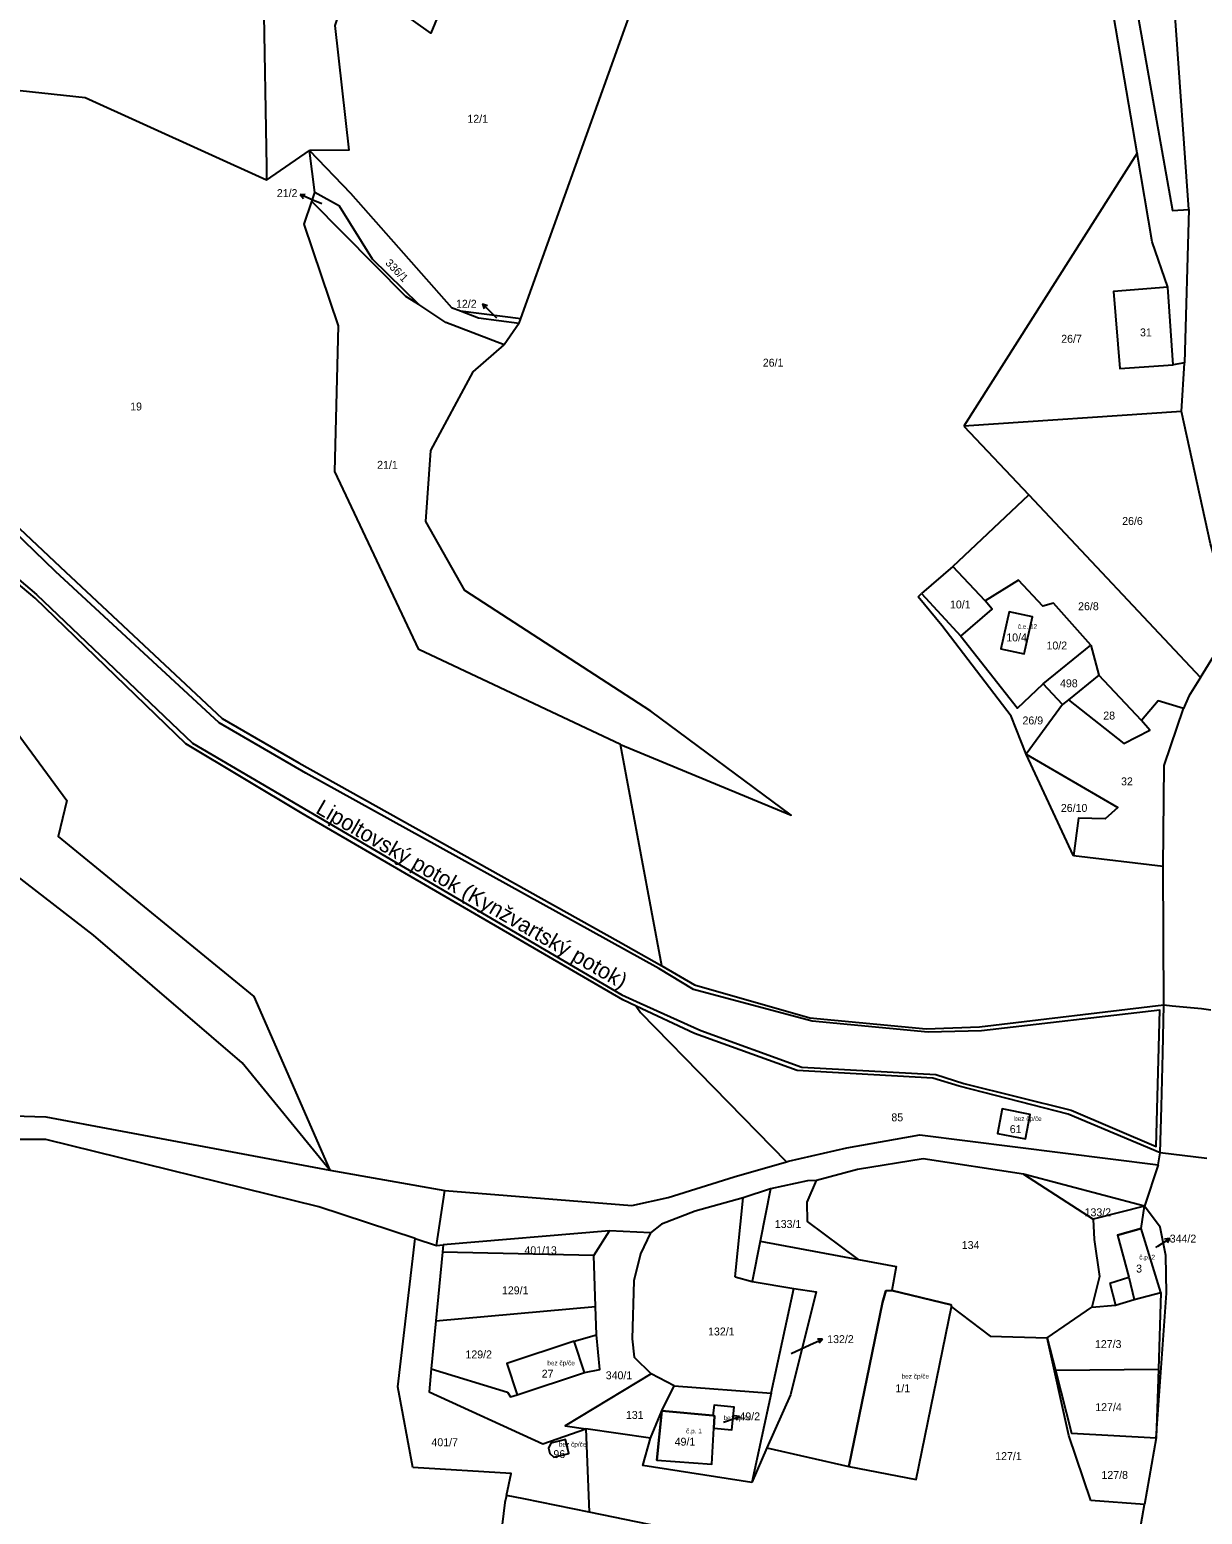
# Model space of a CAD drawing. Extents: x -880531 to -877616, y -1023932 to -1021350.
# Drawn here: x -879033.3 to -878781.4, y -1022605.2 to -1022286.3 of the extents above; entities that cross this region are included whole.
import ezdxf

# ---------------------------------------------------------------- set-up
doc = ezdxf.new("R2010")
doc.units = 0
for name, color, linetype in [('Definiční body', 7, 'Continuous'), ('Hranice parcel', 7, 'Continuous'), ('Parcelní čísla', 7, 'Continuous'), ('Polygon budovy', 7, 'Continuous'), ('Pop  PČ popisy', 7, 'Continuous'), ('Vnitřní kresba', 7, 'Continuous')]:
    doc.layers.add(name, color=color, linetype=linetype)

msp = doc.modelspace()

# ---------------------------------------------------------------- linework, layer by layer
at = {"layer": 'Hranice parcel'}
for p, q in [((-878983.84, -1022237.15), (-878982.48, -1022315.78)), ((-878982.43, -1022318.67), (-878973.23, -1022312.29)), ((-878972.06, -1022321.28), (-878973.23, -1022312.29)), ((-878795.44, -1022312.88), (-878832.67, -1022371.46)), ((-878982.48, -1022315.78), (-878982.43, -1022318.67)), ((-878972.71, -1022323.22), (-878972.06, -1022321.28)), ((-878952.55, -1022343.62), (-878972.71, -1022323.22)), ((-878784.33, -1022324.92), (-878785.28, -1022357.92)), ((-878787.68, -1022358.31), (-878788.89, -1022341.63)), ((-878949.75, -1022345.38), (-878952.55, -1022343.62)), ((-878940.78, -1022346.72), (-878927.84, -1022348.34)), ((-878928.2, -1022349.35), (-878931.42, -1022354.03)), ((-878928.2, -1022349.35), (-878927.84, -1022348.34)), ((-878785.28, -1022357.92), (-878787.68, -1022358.31)), ((-878785.9, -1022368.31), (-878785.28, -1022357.92)), ((-878785.9, -1022368.31), (-878832.67, -1022371.46)), ((-878832.67, -1022371.46), (-878818.74, -1022386.26)), ((-878835.03, -1022401.6), (-878818.74, -1022386.26)), ((-878818.74, -1022386.26), (-878781.84, -1022425.46)), ((-878835.03, -1022401.6), (-878841.76, -1022407.46)), ((-878828.12, -1022408.97), (-878835.03, -1022401.6)), ((-878842.48, -1022408.12), (-878841.76, -1022407.46)), ((-878841.76, -1022407.46), (-878833.29, -1022416.57)), ((-878781.84, -1022425.46), (-878774.74, -1022413.92)), ((-878815.61, -1022426.85), (-878805.41, -1022418.49)), ((-878805.41, -1022418.49), (-878803.69, -1022424.99)), ((-878803.69, -1022424.99), (-878810.22, -1022430.23)), ((-878794.51, -1022434.71), (-878803.69, -1022424.99)), ((-878811.51, -1022431.28), (-878815.61, -1022426.85)), ((-878811.51, -1022431.28), (-878819.3, -1022441.9)), ((-878810.22, -1022430.23), (-878811.51, -1022431.28)), ((-878819.3, -1022441.9), (-878822.5, -1022433.77)), ((-878897.53, -1022487.39), (-878906.39, -1022439.86)), ((-878809.09, -1022463.75), (-878819.3, -1022441.9)), ((-878789.87, -1022466.03), (-878809.09, -1022463.75)), ((-878789.71, -1022495.74), (-878789.87, -1022466.03)), ((-878906.92, -1022482.11), (-878897.53, -1022487.39)), ((-878897.53, -1022487.39), (-878890.53, -1022491.49)), ((-878903.04, -1022496.06), (-878905.93, -1022494.73)), ((-878890.49, -1022501.93), (-878903.04, -1022496.06)), ((-878829.33, -1022500.46), (-878789.71, -1022495.74)), ((-878790.48, -1022527.57), (-878810.27, -1022519.27)), ((-878790.9, -1022530.1), (-878790.48, -1022527.57)), ((-878780.45, -1022528.79), (-878790.48, -1022527.57)), ((-878790.9, -1022530.1), (-878793.85, -1022539.01)), ((-878819.85, -1022532.12), (-878804.9, -1022541.8)), ((-878793.85, -1022539.01), (-878819.85, -1022532.12)), ((-878874.2, -1022535.28), (-878876.43, -1022546.54)), ((-878793.85, -1022539.01), (-878804.9, -1022541.8)), ((-878954.24, -1022577.83), (-878950.5, -1022545.95)), ((-878944.47, -1022547.33), (-878944.62, -1022548.91)), ((-878908.77, -1022544.3), (-878944.47, -1022547.33)), ((-878912.11, -1022549.61), (-878908.77, -1022544.3)), ((-878899.97, -1022544.75), (-878908.77, -1022544.3)), ((-878876.43, -1022546.54), (-878855.28, -1022550.47)), ((-878944.62, -1022548.91), (-878946.05, -1022563.67)), ((-878912.11, -1022549.61), (-878944.62, -1022548.91)), ((-878911.78, -1022560.56), (-878912.11, -1022549.61)), ((-878874.07, -1022579.19), (-878869.18, -1022556.66)), ((-878790.36, -1022557.58), (-878790.88, -1022574.05)), ((-878946.05, -1022563.67), (-878911.78, -1022560.56)), ((-878814.79, -1022567.26), (-878805.18, -1022560.73)), ((-878946.05, -1022563.67), (-878947.05, -1022573.92)), ((-878810.15, -1022588.25), (-878814.79, -1022567.26)), ((-878814.79, -1022567.26), (-878813.01, -1022574.24)), ((-878928.61, -1022579.51), (-878914.14, -1022574.71)), ((-878894.88, -1022577.62), (-878899.79, -1022575.02)), ((-878813.01, -1022574.24), (-878790.88, -1022574.05)), ((-878790.88, -1022574.05), (-878791.35, -1022588.77)), ((-878951.01, -1022595.12), (-878954.24, -1022577.83)), ((-878897.54, -1022582.98), (-878894.88, -1022577.62)), ((-878894.88, -1022577.62), (-878874.07, -1022579.19)), ((-878874.07, -1022579.19), (-878878.23, -1022598.34)), ((-878900, -1022588.81), (-878897.54, -1022582.98)), ((-878900, -1022588.81), (-878913.86, -1022586.8)), ((-878913.86, -1022586.8), (-878913.11, -1022604.75)), ((-878805.38, -1022602.2), (-878810.15, -1022588.25)), ((-878791.35, -1022588.77), (-878793.89, -1022603.11)), ((-878875, -1022590.92), (-878878.23, -1022598.34)), ((-878927.16, -1022601.89), (-878930.92, -1022601.13)), ((-878913.11, -1022604.75), (-878927.16, -1022601.89)), ((-878793.89, -1022603.11), (-878805.38, -1022602.2)), ((-878798.29, -1022627.98), (-878793.89, -1022603.11)), ((-878892.61, -1022608.92), (-878913.11, -1022604.75))]:
    msp.add_line(p, q, dxfattribs=at)
for points in [[(-878784.33, -1022324.92), (-878787.28, -1022283.42), (-878794.14, -1022244.21), (-878808.27, -1022188.07), (-878812.9, -1022166.07), (-878813.77, -1022149.07), (-878813.39, -1022128.85)], [(-878983.84, -1022237.15), (-878937.9, -1022264.69), (-878947.13, -1022287.08), (-878964.25, -1022274.82), (-878967.78, -1022285.4), (-878964.77, -1022312.19), (-878973.23, -1022312.29)], [(-878795.44, -1022312.88), (-878800.43, -1022283.55), (-878807.1, -1022263.29), (-878825.36, -1022240.03)], [(-878927.84, -1022348.34), (-878904.21, -1022282.53), (-878902.68, -1022268.58)], [(-878796.06, -1022278.81), (-878787.83, -1022325.15), (-878784.33, -1022324.92)], [(-878982.43, -1022318.67), (-879021.4, -1022300.98), (-879077.31, -1022294.97), (-879120.32, -1022305.15), (-879151.81, -1022322.15)], [(-878973.23, -1022312.29), (-878964.4, -1022321.44), (-878942.7, -1022345.99), (-878940.78, -1022346.72)], [(-878788.89, -1022341.63), (-878792.2, -1022331.9), (-878795.44, -1022312.88)], [(-878906.39, -1022439.86), (-878949.76, -1022419.42), (-878967.76, -1022381.19), (-878966.97, -1022349.97), (-878974.34, -1022328.1), (-878972.71, -1022323.22)], [(-878949.75, -1022345.38), (-878959.65, -1022335.6), (-878966.79, -1022324.27), (-878972.06, -1022321.28)], [(-879146.4, -1022333.58), (-879145.24, -1022333.35), (-879138.95, -1022339.75), (-879122.89, -1022349.24), (-879116.77, -1022357.07), (-879102.22, -1022354.24), (-879093.28, -1022354.46), (-879071.03, -1022361.28), (-879058.07, -1022372.29), (-879026.73, -1022401.71), (-878991.96, -1022434.26), (-878975.52, -1022443.78), (-878906.92, -1022482.11)], [(-878788.89, -1022341.63), (-878800.5, -1022342.54), (-878799.2, -1022359.11), (-878787.68, -1022358.31)], [(-878931.42, -1022354.03), (-878943.96, -1022349.2), (-878949.75, -1022345.38)], [(-878940.78, -1022346.72), (-878936.92, -1022348.2), (-878928.2, -1022349.35)], [(-878906.39, -1022439.86), (-878869.75, -1022455.04), (-878899.88, -1022432.7), (-878939.85, -1022406.75), (-878948.22, -1022391.94), (-878947.12, -1022376.7), (-878938.05, -1022359.85), (-878931.42, -1022354.03)], [(-878774.74, -1022413.92), (-878779.71, -1022396.76), (-878785.9, -1022368.31)], [(-878905.93, -1022494.73), (-878974.79, -1022454.7), (-878999.79, -1022439.69), (-879032.14, -1022408.46), (-879064.88, -1022380.92)], [(-879246.33, -1022468.23), (-879223.81, -1022468.41), (-879209.64, -1022456.73), (-879209.06, -1022442.32), (-879220.96, -1022441.45), (-879226.56, -1022432.02), (-879197.08, -1022419.54), (-879173.11, -1022403.96), (-879151.46, -1022395.72), (-879080.65, -1022400.74), (-879047.37, -1022421.96), (-879025.33, -1022451.91), (-879027.21, -1022459.61), (-878985.13, -1022493.99), (-878968.86, -1022531.3)], [(-878805.41, -1022418.49), (-878813.42, -1022409.51), (-878815.71, -1022410.18), (-878820.92, -1022404.54), (-878828.12, -1022408.97)], [(-878822.5, -1022433.77), (-878837.39, -1022414.3), (-878842.48, -1022408.12)], [(-878833.29, -1022416.57), (-878826.56, -1022410.79), (-878828.12, -1022408.97)], [(-878819.72, -1022420.4), (-878817.94, -1022412.47), (-878822.93, -1022411.38), (-878824.7, -1022419.31), (-878819.72, -1022420.4)], [(-878833.29, -1022416.57), (-878821.16, -1022432.02), (-878815.61, -1022426.85)], [(-878781.84, -1022425.46), (-878784.38, -1022429.45), (-878785.49, -1022432.12)], [(-878968.86, -1022531.3), (-878987.7, -1022508.24), (-879019.63, -1022480.84), (-879053.22, -1022454.85), (-879091.78, -1022435.29), (-879121.6, -1022427.16), (-879139.91, -1022427.41), (-879176.5, -1022437.82), (-879213.92, -1022466.57), (-879240.35, -1022492.73)], [(-878810.22, -1022430.23), (-878798.27, -1022439.62), (-878792.73, -1022436.79), (-878794.51, -1022434.71)], [(-878785.49, -1022432.12), (-878790.9, -1022430.47), (-878794.51, -1022434.71)], [(-878789.87, -1022466.03), (-878789.64, -1022444.4), (-878785.49, -1022432.12)], [(-878819.3, -1022441.9), (-878799.62, -1022453.37), (-878802.29, -1022455.82), (-878808.03, -1022455.69), (-878809.09, -1022463.75)], [(-879240.35, -1022492.73), (-879219.37, -1022499.31), (-879189.31, -1022507.6), (-879143.86, -1022518.99), (-879124.64, -1022519.3), (-879090.74, -1022517.98), (-879029.81, -1022519.8), (-878968.86, -1022531.3)], [(-878890.53, -1022491.49), (-878865.74, -1022498.56), (-878840.73, -1022500.92), (-878829.33, -1022500.46)], [(-878903.04, -1022496.06), (-878902.14, -1022497.38), (-878870.78, -1022529.52)], [(-878789.71, -1022495.74), (-878787.92, -1022495.97), (-878781.61, -1022496.55), (-878779.59, -1022496.84)], [(-878810.27, -1022519.27), (-878833.7, -1022513.24), (-878839.3, -1022511.51), (-878868.46, -1022509.85), (-878890.49, -1022501.93)], [(-878824.47, -1022518.13), (-878825.44, -1022523.37), (-878819.41, -1022524.58), (-878818.45, -1022519.32), (-878824.47, -1022518.13)], [(-878950.5, -1022545.95), (-878971.2, -1022539.15), (-879029.87, -1022524.72), (-879091.18, -1022524.72), (-879125.05, -1022524.64), (-879137.04, -1022524.47)], [(-878870.78, -1022529.52), (-878870.31, -1022529.36), (-878857.82, -1022526.5), (-878842.1, -1022523.72), (-878790.9, -1022530.1)], [(-878968.86, -1022531.3), (-878944.13, -1022535.68), (-878904.01, -1022538.84), (-878896.15, -1022537.15), (-878882, -1022532.68), (-878870.78, -1022529.52)], [(-878819.85, -1022532.12), (-878841.38, -1022528.85), (-878855.5, -1022531.14), (-878864.32, -1022533.49)], [(-878864.32, -1022533.49), (-878866.26, -1022533.59), (-878874.2, -1022535.28)], [(-878855.28, -1022550.47), (-878866.25, -1022542.28), (-878866.29, -1022538.12), (-878864.32, -1022533.49)], [(-878874.2, -1022535.28), (-878880.06, -1022537.19), (-878890.37, -1022540.08), (-878897.59, -1022542.89), (-878899.97, -1022544.75)], [(-878790.36, -1022557.58), (-878794.55, -1022543.83), (-878793.85, -1022539.01)], [(-878791.35, -1022588.77), (-878789.13, -1022557.69), (-878789.25, -1022549.59), (-878790.51, -1022543.52), (-878793.85, -1022539.01)], [(-878804.9, -1022541.8), (-878804.65, -1022546.14), (-878803.56, -1022554.08), (-878805.18, -1022560.73)], [(-878950.5, -1022545.95), (-878945.94, -1022547.45), (-878944.47, -1022547.33)], [(-878899.97, -1022544.75), (-878902.13, -1022549.27), (-878903.53, -1022555.04), (-878903.94, -1022567.48), (-878903.5, -1022571.42), (-878899.79, -1022575.02)], [(-878876.43, -1022546.54), (-878878.11, -1022555.16), (-878869.18, -1022556.66)], [(-878855.28, -1022550.47), (-878847.22, -1022551.99), (-878848.16, -1022557.1), (-878835.38, -1022560.22), (-878835.34, -1022560.66)], [(-878869.18, -1022556.66), (-878864.38, -1022557.39), (-878869.9, -1022579.5), (-878875, -1022590.92)], [(-878805.18, -1022560.73), (-878800.07, -1022560.3), (-878796.12, -1022559.09), (-878790.36, -1022557.58)], [(-878914.14, -1022574.71), (-878910.85, -1022574.11), (-878911.59, -1022566.66), (-878911.78, -1022560.56)], [(-878875, -1022590.92), (-878857.37, -1022594.95), (-878842.89, -1022597.7), (-878835.34, -1022560.66)], [(-878835.34, -1022560.66), (-878827.03, -1022566.93), (-878814.79, -1022567.26)], [(-878914.14, -1022574.71), (-878916.36, -1022568.02), (-878930.83, -1022572.82), (-878928.61, -1022579.51)], [(-878947.05, -1022573.92), (-878947.54, -1022578.9), (-878923.09, -1022590.07), (-878913.86, -1022586.8)], [(-878947.05, -1022573.92), (-878930.67, -1022578.96), (-878930.03, -1022579.98), (-878928.61, -1022579.51)], [(-878899.79, -1022575.02), (-878918.27, -1022586.16), (-878913.86, -1022586.8)], [(-878813.01, -1022574.24), (-878809.56, -1022587.75), (-878791.35, -1022588.77)], [(-878886.22, -1022584.02), (-878886.37, -1022586.66), (-878882.53, -1022587.04), (-878882.02, -1022582.21), (-878886.31, -1022581.76), (-878886.58, -1022583.99), (-878886.22, -1022584.02)], [(-878921.6, -1022592.14), (-878920.71, -1022592.91), (-878917.51, -1022592.12), (-878918.24, -1022589.14), (-878921.39, -1022589.92), (-878921.9, -1022590.97), (-878921.6, -1022592.14)], [(-878878.23, -1022598.34), (-878901.65, -1022594.69), (-878900, -1022588.81)], [(-878930.92, -1022601.13), (-878929.86, -1022596.43), (-878951.01, -1022595.12)], [(-878930.92, -1022601.13), (-878931.26, -1022602.62), (-878934.82, -1022632.19)]]:
    msp.add_lwpolyline(points, dxfattribs=at)
at = {"layer": 'Polygon budovy'}
for points in [[(-878824.7, -1022419.31), (-878819.72, -1022420.4), (-878817.94, -1022412.47), (-878822.93, -1022411.38)], [(-878819.41, -1022524.58), (-878818.45, -1022519.32), (-878824.47, -1022518.13), (-878825.44, -1022523.37)], [(-878796.12, -1022559.09), (-878790.36, -1022557.58), (-878794.55, -1022543.83), (-878799.69, -1022545.26), (-878797.25, -1022554.28)], [(-878857.37, -1022594.95), (-878842.89, -1022597.7), (-878835.34, -1022560.66), (-878835.38, -1022560.22), (-878848.16, -1022557.1), (-878849.44, -1022557.17), (-878850.17, -1022559.7)], [(-878916.36, -1022568.02), (-878930.83, -1022572.82), (-878928.61, -1022579.51), (-878914.14, -1022574.71)], [(-878882.53, -1022587.04), (-878882.02, -1022582.21), (-878886.31, -1022581.76), (-878886.58, -1022583.99), (-878886.22, -1022584.02), (-878886.37, -1022586.66)], [(-878886.37, -1022586.66), (-878886.22, -1022584.02), (-878886.58, -1022583.99), (-878897.54, -1022582.98), (-878898.62, -1022593.53), (-878886.82, -1022594.4)], [(-878918.24, -1022589.14), (-878921.39, -1022589.92), (-878921.9, -1022590.97), (-878921.6, -1022592.14), (-878920.71, -1022592.91), (-878917.51, -1022592.12)]]:
    msp.add_lwpolyline(points, close=True, dxfattribs=at)
at = {"layer": 'Pop  PČ popisy'}
for p, q in [((-878975.242, -1022321.757), (-878974.125, -1022321.688)), ((-878972.48, -1022322.93), (-878975.242, -1022321.757)), ((-878975.242, -1022321.757), (-878974.516, -1022322.61)), ((-878970.58, -1022323.75), (-878972.48, -1022322.93)), ((-878933.92, -1022347.33), (-878936.042, -1022345.208)), ((-878936.042, -1022345.208), (-878934.98, -1022345.562)), ((-878936.042, -1022345.208), (-878935.688, -1022346.27)), ((-878932.96, -1022348.29), (-878933.92, -1022347.33)), ((-878790.97, -1022547.58), (-878788.453, -1022545.946)), ((-878788.453, -1022545.946), (-878789.566, -1022546.071)), ((-878788.453, -1022545.946), (-878789.02, -1022546.911)), ((-878791.42, -1022547.87), (-878790.97, -1022547.58)), ((-878869.78, -1022570.63), (-878865.74, -1022568.81)), ((-878865.74, -1022568.81), (-878862.998, -1022567.589)), ((-878862.998, -1022567.589), (-878864.117, -1022567.539)), ((-878862.998, -1022567.589), (-878863.71, -1022568.454)), ((-878884.26, -1022585.4), (-878883.68, -1022585.19)), ((-878883.68, -1022585.19), (-878880.86, -1022584.164)), ((-878880.86, -1022584.164), (-878881.972, -1022584.036)), ((-878880.86, -1022584.164), (-878881.63, -1022584.977))]:
    msp.add_line(p, q, dxfattribs=at)
at = {"layer": 'Vnitřní kresba'}
for p, q in [((-878789.96, -1022506.18), (-878789.71, -1022495.74)), ((-878790.24, -1022517.62), (-878789.96, -1022506.18)), ((-878790.48, -1022527.57), (-878790.24, -1022517.62)), ((-878945.94, -1022547.45), (-878944.13, -1022535.68)), ((-878881.78, -1022554.21), (-878880.06, -1022537.19)), ((-878799.69, -1022545.26), (-878794.55, -1022543.83)), ((-878799.69, -1022545.26), (-878797.25, -1022554.28)), ((-878881.78, -1022554.21), (-878878.11, -1022555.16)), ((-878801.28, -1022555.52), (-878797.25, -1022554.28)), ((-878801.28, -1022555.52), (-878800.07, -1022560.3)), ((-878797.25, -1022554.28), (-878796.12, -1022559.09)), ((-878857.37, -1022594.95), (-878850.17, -1022559.7)), ((-878850.17, -1022559.7), (-878849.44, -1022557.17)), ((-878849.44, -1022557.17), (-878848.16, -1022557.1)), ((-878916.36, -1022568.02), (-878911.59, -1022566.66)), ((-878898.62, -1022593.53), (-878897.54, -1022582.98)), ((-878897.54, -1022582.98), (-878886.58, -1022583.99)), ((-878886.82, -1022594.4), (-878886.37, -1022586.66)), ((-878898.62, -1022593.53), (-878886.82, -1022594.4))]:
    msp.add_line(p, q, dxfattribs=at)
for points in [[(-879027.78, -1022402.72), (-879058.96, -1022372.59), (-879071.52, -1022362.09), (-879092.98, -1022355.25), (-879101.73, -1022354.93), (-879116.99, -1022357.79), (-879123.51, -1022349.68), (-879139.25, -1022340.45), (-879144.98, -1022334.41), (-879158.17, -1022336.48)], [(-879160.96, -1022349.83), (-879149.97, -1022340.97), (-879141.38, -1022344.31), (-879126.59, -1022355.93), (-879124.84, -1022361.97), (-879117.21, -1022368.97), (-879099.88, -1022365.31), (-879084.46, -1022374.7), (-879064.11, -1022380.26), (-879031.83, -1022407.63), (-878998.37, -1022439.56), (-878906.15, -1022493.65), (-878902.18, -1022495.4), (-878889.14, -1022501.28), (-878867.5, -1022509.14)], [(-878867.5, -1022509.14), (-878838.72, -1022510.73), (-878832.68, -1022512.64), (-878809.62, -1022518.37), (-878791.34, -1022526.16), (-878790.54, -1022496.89), (-878828.86, -1022501.35), (-878840.31, -1022501.67), (-878865.27, -1022499.28), (-878890.71, -1022492.44), (-878898.19, -1022487.98), (-878973.99, -1022446.01), (-878992.62, -1022435.19), (-879027.78, -1022402.72)]]:
    msp.add_lwpolyline(points, dxfattribs=at)

# ---------------------------------------------------------------- texts
at = {"layer": 'Definiční body'}
for s, p in [('č.e. 12', (-878821.07, -1022415.01)), ('bez čp/če', (-878821.86, -1022520.71)), ('č.p. 2', (-878794.99, -1022550.46)), ('bez čp/če', (-878922.13, -1022573.19)), ('bez čp/če', (-878846.04, -1022576.05)), ('bez čp/če', (-878884.28, -1022584.97)), ('č.p. 1', (-878892.32, -1022587.8)), ('bez čp/če', (-878919.64, -1022590.66))]:
    msp.add_text(s, height=1, dxfattribs=at).set_placement(p)
at = {"layer": 'Parcelní čísla'}
for s, p in [('12/1', (-878939.29, -1022306.32)), ('21/2', (-878980.223, -1022322.28)), ('12/2', (-878941.737, -1022346.05)), ('26/7', (-878811.75, -1022353.57)), ('31', (-878794.83, -1022352.2)), ('26/1', (-878875.85, -1022358.7)), ('19', (-879011.72, -1022368.11)), ('21/1', (-878958.68, -1022380.64)), ('26/6', (-878798.66, -1022392.7)), ('10/1', (-878835.64, -1022410.63)), ('26/8', (-878808.12, -1022411.01)), ('10/4', (-878823.56, -1022417.71)), ('10/2', (-878814.91, -1022419.45)), ('498', (-878812.009, -1022427.56)), ('26/9', (-878820.07, -1022435.54)), ('28', (-878802.72, -1022434.49)), ('32', (-878798.9, -1022448.63)), ('26/10', (-878811.83, -1022454.33)), ('85', (-878848.23, -1022520.78)), ('61', (-878822.8, -1022523.31)), ('133/2', (-878806.73, -1022541.18)), ('133/1', (-878873.27, -1022543.69)), ('134', (-878833.11, -1022548.21)), ('344/2', (-878788.44, -1022546.82)), ('401/13', (-878927.044, -1022549.33)), ('3', (-878795.66, -1022553.26)), ('129/1', (-878931.87, -1022557.94)), ('132/1', (-878887.6, -1022566.78)), ('132/2', (-878862.01, -1022568.42)), ('127/3', (-878804.51, -1022569.48)), ('129/2', (-878939.71, -1022571.7)), ('27', (-878923.34, -1022575.84)), ('340/1', (-878909.58, -1022576.19)), ('1/1', (-878847.36, -1022578.97)), ('127/4', (-878804.44, -1022583.03)), ('131', (-878905.25, -1022584.71)), ('49/2', (-878880.86, -1022585.01)), ('401/7', (-878947.013, -1022590.56)), ('49/1', (-878894.78, -1022590.45)), ('96', (-878920.82, -1022593.11)), ('127/1', (-878825.93, -1022593.54)), ('127/8', (-878803.107, -1022597.59))]:
    msp.add_text(s, height=1.7, dxfattribs=at).set_placement(p)
msp.add_text('336/1', height=1.7, rotation=314, dxfattribs=at).set_placement((-878957.031, -1022336.57))
at = {"layer": 'Pop  PČ popisy'}
msp.add_text('Lipoltovský potok (Kynžvartský potok)', height=3.4, rotation=330, dxfattribs=at).set_placement((-878972.1, -1022454.439))

doc.saveas('drawing.dxf')
